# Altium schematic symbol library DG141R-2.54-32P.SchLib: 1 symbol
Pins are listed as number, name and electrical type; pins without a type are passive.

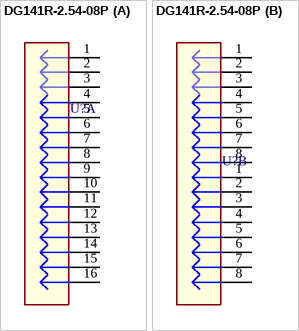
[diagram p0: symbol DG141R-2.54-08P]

## DG141R-2.54-08P
designator U?  (value not drawn)
DG129-5.0-03P-14-00AH
footprint DG141R-2.54-08P
part A pins: 1, 2, 3, 4, 5, 6, 7, 8, 9, 10, 11, 12, 13, 14, 15, 16
part B pins: 1, 1, 2, 2, 3, 3, 4, 4, 5, 5, 6, 6, 7, 7, 8, 8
